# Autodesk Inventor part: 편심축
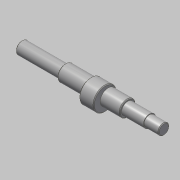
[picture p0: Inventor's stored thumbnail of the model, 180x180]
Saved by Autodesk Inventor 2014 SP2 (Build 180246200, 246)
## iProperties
Created: 2016-05
Part Number: 편심축
Document SubType Name: Modeling
Designer: mduedu
Density: 7.86 g/cm^3
Material: 강철, 연강
Appearance: 강철
Author: mduedu
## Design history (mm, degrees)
sketch "스케치1"
  geometry: L1 (-38, 11)-(-38, 8.5); L2 (48, 11)-(48, 8.5); L3 (-98, 0)-(98, 0); L4 (-38, 11)-(48, 11); L5 (48, 11)-(48, 8.5); L6 (-38, 11)-(-38, 8.5); L7 (-38, 8.5)-(-98, 8.5); L8 (-98, 8.5)-(-98, 0); L9 (48, 8.5)-(78, 8.5); L10 (98, 7.5)-(98, 0); L11 (78, 8.5)-(78, 7.5); L12 (78, 7.5)-(98, 7.5); 1 further point
  constraints: 24 end point, 9 perpendicular, 2 midpoint, 1 collinear, 1 horizontal
  dimensions: "d0" = 22 diameter of L4 L3; "d1" = 17 diameter of L7 L3; "d2" = 60 distance between parallel lines of L8 L1; "d3" = 50 distance between parallel lines of L10 L2; "d4" = 15 diameter of L12 L3; "d5" = 20 distance between parallel lines of L10 L11; "d29" = 86 distance of L1.start L2.start
revolve "회전1" stored, may be unused: angle "d6" = 90 deg
node "작업 평면7"
node "작업 평면9"
sketch "스케치2"
  geometry: C1 r 11 at (0, 0); C2 r 16 at (0, -4); C3 r 11 at (0, 0); 2 further points
  constraints: 3 centre point, 2 coincident, 1 concentric, 1 vertical alignment
  dimensions: "d9" = 4 distance of point (0, 0) C2.centre; "d10" = 32 diameter of C2
extrude "돌출1" join sketch "스케치2" stored distance "d11" = 20; taper "d12" = 0 deg
chamfer "모따기1" distance "d17" = 1; stored, may be unused: second distance "d18" = 2, angle "d19" = 45 deg
node "작업 평면4"
sketch "스케치4"
  geometry: L1 (-10, -6.5)-(-10, 6.5) reference; L2 (-5, 2.5)-(5, 2.5); L3 (5, -2.5)-(-5, -2.5); A1 r 2.5 centre (5, 0) between (5, -2.5) and (5, 2.5); A2 r 2.5 centre (-5, 0) between (-5, 2.5) and (-5, -2.5); 2 further points
  constraints: 4 end point, 4 point on circle, 4 tangent, 2 centre point, 1 horizontal alignment, 1 midpoint, 1 parallel, 1 perpendicular
  dimensions: "d20" = 5 distance between parallel lines of L3 L2; "d21" = 15 dimension on A1 A2; "d22" = 2.5 distance edge to line of A2 L1
extrude "돌출3" cut sketch "스케치4" distance "d23" = 3; taper "d24" = 0 deg
node "작업 평면5"
sketch "스케치5"
  geometry: L1 (30, 7.5)-(30, -7.5) reference; L2 (30, 2.5)-(12.5, 2.5); L3 (12.5, -2.5)-(30, -2.5); A1 r 2.5 centre (12.5, 0) between (12.5, 2.5) and (12.5, -2.5); 2 further points
  constraints: 4 end point, 2 perpendicular, 2 point on circle, 2 point on line, 2 tangent, 1 centre point, 1 horizontal alignment, 1 midpoint
  dimensions: "d25" = 5 distance between parallel lines of L3 L2; "d26" = 20 dimension on A1 L1
extrude "돌출4" cut sketch "스케치5" distance "d27" = 3; taper "d28" = 0 deg
node "솔리드1"
other parameters: "d31" = -37
